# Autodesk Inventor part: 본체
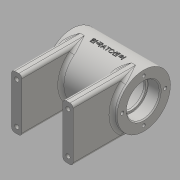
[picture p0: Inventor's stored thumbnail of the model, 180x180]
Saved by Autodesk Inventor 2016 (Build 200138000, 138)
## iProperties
Created: 2020-07
Part Number: 본체
Material: 일반
Document SubType Name: Modeling
Designer: 605-12
Density: 1 g/cm^3
Appearance: 기본값
Author: 605-12
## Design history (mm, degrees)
sketch "스케치1"
  geometry: 1 further point
sketch "스케치3"
  geometry: L1 (35, 0)-(-35, 0); L2 (35, 0)-(35, 26); L3 (35, 26)-(-35, 26); L4 (-35, 26)-(-35, 0); L5 (35, 16)-(23, 16); L6 (23, 16)-(23, 14); L7 (23, 14)-(21, 14); L8 (21, 14)-(21, 21); L9 (21, 21)-(-21, 21); L10 (-21, 21)-(-21, 14); L11 (-21, 14)-(-23, 14); L12 (-23, 14)-(-23, 16); L13 (-23, 16)-(-35, 16); 2 further points
  constraints: 26 end point, 11 perpendicular, 2 point on line, 1 coincident, 1 horizontal, 1 midpoint, 1 vertical
  dimensions: "d1" = 32 diameter of L13 L1; "d2" = 52 diameter of L3 L1; "d3" = 28 diameter of L11 L1; "d4" = 42 diameter of L9 L1; "d5" = 28 diameter of L7 L1; "d6" = 32 diameter of L5 L1; "d7" = 70 distance of L2.end L3.end; "d8" = 12 distance of L5.start L5.end; "d9" = 2 distance of L6.end L7.end; "d10" = 42 distance of L8.end L9.end; "d11" = 2 distance of L10.end L11.end
revolve "회전1" sketch "스케치3" stored, may be unused: angle "d12" = 90 deg
node "작업 평면2"
sketch "스케치4"
  geometry: L1 (30, -26)-(20, -26); L2 (20, -26)-(20, 26); L3 (20, 26)-(30, 26); L4 (30, 26)-(30, -26); L5 (-20, -26)-(-30, -26); L6 (-30, -26)-(-30, 26); L7 (-30, 26)-(-20, 26); L8 (-20, 26)-(-20, -26); 3 further points
  constraints: 16 end point, 4 parallel, 2 horizontal, 2 horizontal alignment, 2 midpoint, 2 perpendicular
  dimensions: "d14" = 10 distance of L1.start L1.end; "d15" = 52 distance of L3.end L1.start; "d16" = 52 distance of L5.end L6.end; "d17" = 20 distance from line of point (0, 0) L2; "d18" = 20 distance from line of L8 point (0, 0); "d19" = 10 distance of L5.start L5.end
extrude "돌출1" join sketch "스케치4" stored distance "d20" = 10; taper "d21" = 0 deg
node "작업 평면3"
chamfer "모따기1" distance "d23" = 1; stored, may be unused: second distance "d24" = 2, angle "d25" = 45 deg
sketch "스케치5"
  geometry: L1 (0, 0)-(0, 21)
  constraints: 2 end point, 1 vertical
  dimensions: "d26" = 21 distance of L1.start L1.end
hole "구멍1" sketch "스케치5" at (0, 21) diameter "d27" = 3.242; stored, may be unused: countersink angle "d31" = 90 deg, drill point angle "d33" = 118 deg; dims "d28" = 8, "d29" = 4, "d30" = 2, "d32" = 10
fillet "모깎기1" dims "d37" = 3
sketch "스케치6"
  geometry: L1 (33, 20.621)-(33, -20.621) reference; L2 (30, -23)-(30, 23) reference; L3 (23, -26)-(27, -26) reference; 2 further points
  dimensions: "d39" = 5 distance from line of L2 point (25, -20); "d40" = 6 distance from line of L3 point (25, -20)
hole "구멍2" sketch "스케치6" at (25, -20) diameter "d41" = 4.134; stored, may be unused: countersink angle "d45" = 90 deg, drill point angle "d47" = 118 deg; dims "d42" = 8, "d43" = 4, "d44" = 2, "d46" = 10
sketch "스케치7"
  geometry: C1 r 5 at (0, 0); 1 further point
  constraints: 1 centre point, 1 coincident
  dimensions: "d54" = 10 diameter of C1
extrude "돌출2" join sketch "스케치7" stored distance "d55" = 10; taper "d56" = 0 deg
hole "구멍3" diameter "d59" = 5.188; stored, may be unused: countersink angle "d63" = 90 deg, drill point angle "d65" = 118 deg; dims "d57" = 10, "d58" = 10, "d60" = 12, "d61" = 4, "d62" = 2, "d64" = 16
fillet "모깎기2" dims "d66" = 2
sketch "스케치10"
  geometry: L1 (0, 0)-(-31.592, 0); L2 (0, 0)-(-27.251, -9.919); L3 (-27.251, -9.919)-(-25.199, -15.557); L4 (-25.199, -15.557)-(-21.72, -14.291); A1 r 26 centre (0, 0) between (-24.432, -8.893) and (-21.72, -14.291)
  constraints: 8 end point, 2 perpendicular, 2 point on circle, 1 centre point, 1 coincident, 1 horizontal, 1 point on line
  dimensions: "d76" = 29 distance of L1.start L2.end; "d78" = 20 deg angle of L2 L1; "d79" = 52 diameter of A1; "d81" = 12 diameter of L4 L2
revolve "회전2" sketch "스케치10" stored, may be unused: angle "d82" = 90 deg
hole "구멍4" diameter "d85" = 5.188; stored, may be unused: countersink angle "d89" = 90 deg, drill point angle "d91" = 118 deg; dims "d83" = 10, "d84" = 10, "d86" = 12, "d87" = 4, "d88" = 2, "d90" = 16
fillet "모깎기3" dims "d92" = 2
fillet "모깎기4" dims "d93" = 0.3
fillet "모깎기5" dims "d94" = 3
node "작업 평면4"
sketch "스케치14"
  geometry: L1 (35, 26)-(-35, 26) reference; L2 (-35, 26)-(-35, -26) reference; 2 further points
  constraints: 1 other
  dimensions: "d101" = 26 distance from line of L1 point (0, 0); "d102" = 35 distance from line of L2 point (0, 0)
feature "엠보싱2" sketch "스케치14" dims "d1" = 32, "d2" = 52, "d3" = 28, "d4" = 42, "d5" = 28, "d6" = 32, "d7" = 70, "d8" = 12, "d9" = 2, "d10" = 42, "d11" = 2, "d14" = 10, "d15" = 52, "d17" = 20, "d103" = 0.5, "d104" = 0
node "솔리드1"
pattern_circular "원형 패턴1" dims angle "d35" = 360 deg
mirror "대칭1"
pattern_linear "직사각형 패턴1" dims "d50" = 40
other parameters: "d13" = -64, "d22" = 29, "d69" = 42, "d71" = 42, "d95" = 0
